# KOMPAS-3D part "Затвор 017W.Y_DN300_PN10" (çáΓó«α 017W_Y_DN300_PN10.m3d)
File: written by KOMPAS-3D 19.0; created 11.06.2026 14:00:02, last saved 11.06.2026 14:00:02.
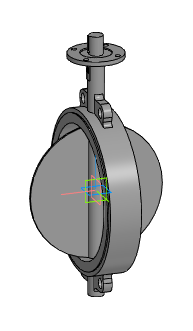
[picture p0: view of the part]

Document properties: Автор: Евгений; Полное имя файла: Z:\3.Личные\kachalov\001_3d для проектировщиков\x.x Тип 017W.Y(S) Затвор дисковый поворотный межфланцевый\_stp_Затвор 017W.Y_DN50-DN350\Затвор 017W_Y_DN300_PN10.m3d

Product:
- Part/product: Затвор 017W.Y_DN300_PN10

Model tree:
1. Операция без истории:1  (labels: Затвор 017W.Y_DN300_PN10)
